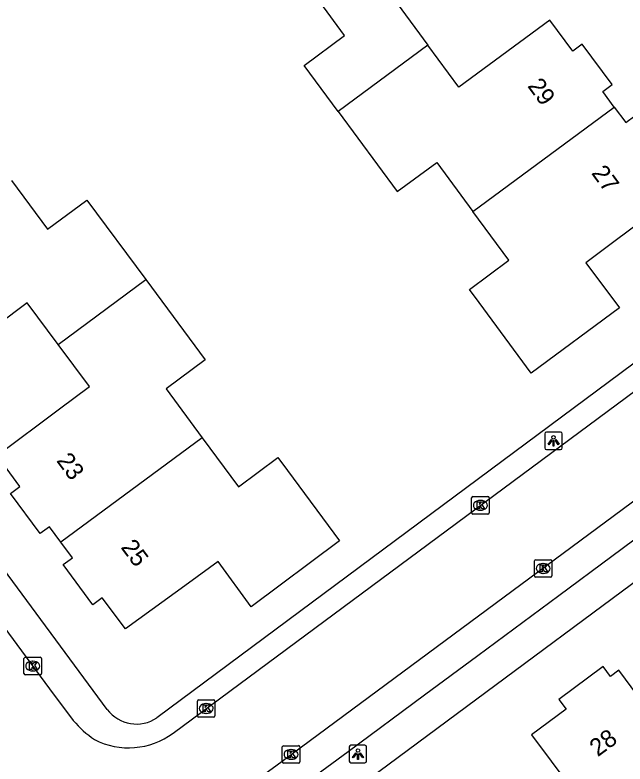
# Model space of a CAD drawing. Extents: x 163427 to 164190, y 380331 to 381641.
# Drawn here: x 163869.78 to 163904.63, y 381127.66 to 381170.43 of the extents above; entities that cross this region are included whole.
import ezdxf

# ---------------------------------------------------------------- set-up
doc = ezdxf.new("R2010")
doc.units = 0
for name, color, linetype in [('IMGEO_Kolk', 7, 'Continuous'), ('IMGEO_Lichtpunt', 7, 'Continuous'), ('IMGEO_Pand', 7, 'Continuous'), ('IMGEO_Pand_nummerreeks', 7, 'Continuous'), ('IMGEO_Rijbaan_lokaal_open', 7, 'Continuous'), ('IMGEO_Voetpad_open', 7, 'Continuous')]:
    doc.layers.add(name, color=color, linetype=linetype)

msp = doc.modelspace()

# ---------------------------------------------------------------- linework, layer by layer
at = {"layer": 'IMGEO_Kolk'}
for p, q in [((163895.865, 381142.004), (163895.865, 381142.856)), ((163895.94, 381142.93), (163896.792, 381142.93)), ((163896.866, 381142.856), (163896.866, 381142.004)), ((163896.353, 381142.71), (163896.378, 381142.71)), ((163896.792, 381141.93), (163895.94, 381141.93)), ((163896.376, 381142.15), (163896.351, 381142.15)), ((163899.526, 381139.324), (163900.378, 381139.324)), ((163899.451, 381138.398), (163899.451, 381139.25)), ((163899.939, 381139.104), (163899.964, 381139.104)), ((163900.452, 381139.25), (163900.452, 381138.398)), ((163899.962, 381138.544), (163899.937, 381138.544)), ((163900.378, 381138.324), (163899.526, 381138.324)), ((163870.372, 381133.748), (163871.224, 381133.748)), ((163870.297, 381132.822), (163870.297, 381133.674)), ((163870.785, 381133.528), (163870.81, 381133.528)), ((163871.298, 381133.674), (163871.298, 381132.822)), ((163870.808, 381132.968), (163870.783, 381132.968)), ((163871.224, 381132.748), (163870.372, 381132.748)), ((163880.205, 381130.401), (163880.205, 381131.253)), ((163880.28, 381131.327), (163881.132, 381131.327)), ((163881.206, 381131.253), (163881.206, 381130.401)), ((163880.693, 381131.107), (163880.718, 381131.107)), ((163881.132, 381130.327), (163880.28, 381130.327)), ((163880.716, 381130.547), (163880.691, 381130.547)), ((163885.052, 381127.777), (163885.052, 381128.629)), ((163885.127, 381128.703), (163885.979, 381128.703)), ((163886.053, 381128.629), (163886.053, 381127.777)), ((163885.54, 381128.483), (163885.565, 381128.483)), ((163885.563, 381127.923), (163885.538, 381127.923)), ((163885.979, 381127.703), (163885.127, 381127.703))]:
    msp.add_line(p, q, dxfattribs=at)
for points in [[(163895.865, 381142.004), (163895.865, 381142.856)], [(163895.94, 381142.93), (163896.792, 381142.93)], [(163896.866, 381142.856), (163896.866, 381142.004)], [(163896.186, 381142.63), (163896.309, 381142.63), (163896.309, 381142.479), (163896.439, 381142.63), (163896.603, 381142.63), (163896.457, 381142.479), (163896.61, 381142.23), (163896.458, 381142.23), (163896.373, 381142.394), (163896.309, 381142.327), (163896.309, 381142.23), (163896.186, 381142.23), (163896.186, 381142.63)], [(163896.792, 381141.93), (163895.94, 381141.93)], [(163899.526, 381139.324), (163900.378, 381139.324)], [(163899.451, 381138.398), (163899.451, 381139.25)], [(163899.772, 381139.024), (163899.895, 381139.024), (163899.895, 381138.873), (163900.025, 381139.024), (163900.189, 381139.024), (163900.043, 381138.873), (163900.196, 381138.624), (163900.044, 381138.624), (163899.959, 381138.788), (163899.895, 381138.721), (163899.895, 381138.624), (163899.772, 381138.624), (163899.772, 381139.024)], [(163900.452, 381139.25), (163900.452, 381138.398)], [(163900.378, 381138.324), (163899.526, 381138.324)], [(163870.372, 381133.748), (163871.224, 381133.748)], [(163870.297, 381132.822), (163870.297, 381133.674)], [(163870.618, 381133.448), (163870.741, 381133.448), (163870.741, 381133.297), (163870.871, 381133.448), (163871.035, 381133.448), (163870.889, 381133.297), (163871.042, 381133.048), (163870.89, 381133.048), (163870.805, 381133.212), (163870.741, 381133.145), (163870.741, 381133.048), (163870.618, 381133.048), (163870.618, 381133.448)], [(163871.298, 381133.674), (163871.298, 381132.822)], [(163871.224, 381132.748), (163870.372, 381132.748)], [(163880.205, 381130.401), (163880.205, 381131.253)], [(163880.28, 381131.327), (163881.132, 381131.327)], [(163881.206, 381131.253), (163881.206, 381130.401)], [(163880.526, 381131.027), (163880.649, 381131.027), (163880.649, 381130.876), (163880.779, 381131.027), (163880.943, 381131.027), (163880.797, 381130.876), (163880.95, 381130.627), (163880.798, 381130.627), (163880.713, 381130.791), (163880.649, 381130.724), (163880.649, 381130.627), (163880.526, 381130.627), (163880.526, 381131.027)], [(163881.132, 381130.327), (163880.28, 381130.327)], [(163885.052, 381127.777), (163885.052, 381128.629)], [(163885.127, 381128.703), (163885.979, 381128.703)], [(163886.053, 381128.629), (163886.053, 381127.777)], [(163885.373, 381128.403), (163885.496, 381128.403), (163885.496, 381128.252), (163885.626, 381128.403), (163885.79, 381128.403), (163885.644, 381128.252), (163885.797, 381128.003), (163885.645, 381128.003), (163885.56, 381128.167), (163885.496, 381128.1), (163885.496, 381128.003), (163885.373, 381128.003), (163885.373, 381128.403)], [(163885.979, 381127.703), (163885.127, 381127.703)]]:
    msp.add_lwpolyline(points, dxfattribs=at)
for centre, start, end in [((163895.942, 381142.854), 91.552, 178.448), ((163895.942, 381142.854), 91.552, 178.448), ((163896.79, 381142.854), 1.552, 88.448), ((163896.79, 381142.854), 1.552, 88.448), ((163895.942, 381142.006), 181.552, 268.448), ((163895.942, 381142.006), 181.552, 268.448), ((163896.79, 381142.006), 271.552, 358.448), ((163896.79, 381142.006), 271.552, 358.448), ((163899.528, 381139.248), 91.552, 178.448), ((163899.528, 381139.248), 91.552, 178.448), ((163900.376, 381139.248), 1.552, 88.448), ((163900.376, 381139.248), 1.552, 88.448), ((163899.528, 381138.4), 181.552, 268.448), ((163899.528, 381138.4), 181.552, 268.448), ((163900.376, 381138.4), 271.552, 358.448), ((163900.376, 381138.4), 271.552, 358.448), ((163870.374, 381133.672), 91.552, 178.448), ((163870.374, 381133.672), 91.552, 178.448), ((163871.222, 381133.672), 1.552, 88.448), ((163871.222, 381133.672), 1.552, 88.448), ((163870.374, 381132.824), 181.552, 268.448), ((163870.374, 381132.824), 181.552, 268.448), ((163871.222, 381132.824), 271.552, 358.448), ((163871.222, 381132.824), 271.552, 358.448), ((163880.282, 381131.251), 91.552, 178.448), ((163880.282, 381131.251), 91.552, 178.448), ((163881.13, 381131.251), 1.552, 88.448), ((163881.13, 381131.251), 1.552, 88.448), ((163880.282, 381130.403), 181.552, 268.448), ((163880.282, 381130.403), 181.552, 268.448), ((163881.13, 381130.403), 271.552, 358.448), ((163881.13, 381130.403), 271.552, 358.448), ((163885.129, 381128.627), 91.552, 178.448), ((163885.129, 381128.627), 91.552, 178.448), ((163885.977, 381128.627), 1.552, 88.448), ((163885.977, 381128.627), 1.552, 88.448), ((163885.129, 381127.779), 181.552, 268.448), ((163885.129, 381127.779), 181.552, 268.448), ((163885.977, 381127.779), 271.552, 358.448), ((163885.977, 381127.779), 271.552, 358.448)]:
    msp.add_arc(centre, 0.0765, start, end, dxfattribs=at)
for centre, major_axis, ratio, start_param, end_param in [((163896.352, 381142.43), (-0.387, 0.002), 0.722429, 4.712389, 7.853982), ((163896.377, 381142.43), (-0.39, 0.002), 0.717154, 1.570796, 4.712389), ((163899.938, 381138.824), (-0.387, 0.002), 0.722429, 4.712389, 7.853982), ((163899.963, 381138.824), (-0.39, 0.002), 0.717154, 1.570796, 4.712389), ((163870.784, 381133.248), (-0.387, 0.002), 0.722429, 4.712389, 7.853982), ((163870.809, 381133.248), (-0.39, 0.002), 0.717154, 1.570796, 4.712389), ((163880.692, 381130.827), (-0.387, 0.002), 0.722429, 4.712389, 7.853982), ((163880.717, 381130.827), (-0.39, 0.002), 0.717154, 1.570796, 4.712389), ((163885.539, 381128.203), (-0.387, 0.002), 0.722429, 4.712389, 7.853982), ((163885.564, 381128.203), (-0.39, 0.002), 0.717154, 1.570796, 4.712389)]:
    msp.add_ellipse(centre, major_axis=major_axis, ratio=ratio, start_param=start_param, end_param=end_param, dxfattribs=at)
at = {"layer": 'IMGEO_Lichtpunt'}
for p, q in [((163900.948, 381146.612), (163900.14, 381146.612)), ((163900.948, 381146.612), (163900.14, 381146.612)), ((163900.046, 381146.517), (163900.046, 381145.71)), ((163900.046, 381146.517), (163900.046, 381145.71)), ((163901.042, 381145.71), (163901.042, 381146.517)), ((163901.042, 381145.71), (163901.042, 381146.517)), ((163900.14, 381145.616), (163900.948, 381145.616)), ((163900.14, 381145.616), (163900.948, 381145.616)), ((163888.873, 381128.628), (163888.873, 381127.821)), ((163888.873, 381128.628), (163888.873, 381127.821)), ((163889.775, 381128.723), (163888.967, 381128.723)), ((163889.775, 381128.723), (163888.967, 381128.723)), ((163889.869, 381127.821), (163889.869, 381128.628)), ((163889.869, 381127.821), (163889.869, 381128.628)), ((163888.967, 381127.727), (163889.775, 381127.727)), ((163888.967, 381127.727), (163889.775, 381127.727))]:
    msp.add_line(p, q, dxfattribs=at)
for points in [[(163900.42, 381146.181), (163900.459, 381146.153), (163900.271, 381145.891), (163900.233, 381145.918), (163900.42, 381146.181)], [(163900.632, 381146.153), (163900.67, 381146.18), (163900.857, 381145.918), (163900.818, 381145.89), (163900.632, 381146.153)], [(163900.522, 381146.133), (163900.569, 381146.133), (163900.569, 381145.811), (163900.522, 381145.811), (163900.522, 381146.133)], [(163889.247, 381128.292), (163889.286, 381128.264), (163889.098, 381128.002), (163889.06, 381128.029), (163889.247, 381128.292)], [(163889.349, 381128.244), (163889.396, 381128.244), (163889.396, 381127.922), (163889.349, 381127.922), (163889.349, 381128.244)], [(163889.459, 381128.264), (163889.497, 381128.291), (163889.684, 381128.029), (163889.645, 381128.001), (163889.459, 381128.264)]]:
    msp.add_lwpolyline(points, dxfattribs=at)
for centre in [(163900.545, 381146.315), (163889.372, 381128.426)]:
    msp.add_circle(centre, 0.0994, dxfattribs=at)
for centre, start, end in [((163900.14, 381146.517), 90, 180), ((163900.14, 381146.517), 90, 180), ((163900.948, 381146.517), 0, 90), ((163900.948, 381146.517), 0, 90), ((163900.14, 381145.71), 180, 270), ((163900.14, 381145.71), 180, 270), ((163900.948, 381145.71), 270, 0), ((163900.948, 381145.71), 270, 360), ((163888.967, 381128.628), 90, 180), ((163888.967, 381128.628), 90, 180), ((163889.775, 381128.628), 0, 90), ((163889.775, 381128.628), 0, 90), ((163888.967, 381127.821), 180, 270), ((163888.967, 381127.821), 180, 270), ((163889.775, 381127.821), 270, 0), ((163889.775, 381127.821), 270, 360)]:
    msp.add_arc(centre, 0.0946, start, end, dxfattribs=at)
at = {"layer": 'IMGEO_Pand'}
for points in [[(163895.984, 381181.97), (163898.336, 381178.777), (163897.808, 381178.385), (163899.116, 381176.624), (163891.604, 381171.094), (163893.368, 381168.698)], [(163888.24, 381164.922), (163886.3, 381167.548), (163888.607, 381169.253), (163887.188, 381171.174), (163889.447, 381172.843), (163887.383, 381175.637)], [(163904.008, 381165.174), (163903.352, 381166.064), (163903.884, 381166.456), (163902.178, 381168.769), (163901.651, 381168.373), (163900.332, 381170.131), (163895.131, 381166.302), (163893.368, 381168.698)], [(163893.368, 381168.698), (163888.24, 381164.922)], [(163904.008, 381165.174), (163904.665, 381164.283), (163905.197, 381164.676), (163906.897, 381162.371), (163906.356, 381161.988), (163907.631, 381160.185), (163904.073, 381157.531), (163902.39, 381156.275), (163904.312, 381153.699), (163899.276, 381149.981), (163896.305, 381154.003), (163895.748, 381154.757), (163898, 381156.42), (163895.936, 381159.214)], [(163895.936, 381159.214), (163904.008, 381165.174)], [(163888.24, 381164.922), (163891.621, 381160.344), (163893.872, 381162.007), (163895.936, 381159.214)], [(163869.581, 381160.987), (163871.647, 381158.2), (163873.888, 381159.861), (163877.25, 381155.325)], [(163872.254, 381151.606), (163877.25, 381155.325)], [(163877.25, 381155.325), (163880.651, 381150.737), (163878.411, 381149.076), (163880.48, 381146.285)], [(163872.254, 381151.606), (163870.475, 381153.999), (163868.764, 381152.726), (163865.197, 381150.072), (163863.893, 381151.842), (163863.362, 381151.451), (163861.664, 381153.74), (163862.196, 381154.135), (163861.533, 381155.029)], [(163872.408, 381140.322), (163871.754, 381141.206), (163871.224, 381140.814), (163869.523, 381143.111), (163870.056, 381143.503), (163868.749, 381145.28), (163872.325, 381147.94), (163874.035, 381149.212), (163872.254, 381151.606)], [(163880.48, 381146.285), (163882.549, 381143.494), (163884.789, 381145.156), (163885.342, 381144.41), (163888.32, 381140.393), (163883.272, 381136.64), (163881.394, 381139.227), (163879.691, 381137.99), (163876.101, 381135.383), (163874.767, 381137.141), (163874.239, 381136.741), (163872.532, 381139.046), (163873.062, 381139.439), (163872.408, 381140.322)], [(163880.48, 381146.285), (163872.408, 381140.322)], [(163911.457, 381128.826), (163908.835, 381126.878), (163907.537, 381128.624), (163904.279, 381133.006), (163903.797, 381132.65), (163903.374, 381133.22), (163900.854, 381131.347), (163901.27, 381130.787), (163899.295, 381129.331), (163903.828, 381123.229)]]:
    msp.add_lwpolyline(points, dxfattribs=at)
at = {"layer": 'IMGEO_Rijbaan_lokaal_open'}
for points in [[(163878.809, 381129.42), (163911.186, 381153.408)], [(163880.923, 381124.832), (163884.68, 381127.548), (163916.554, 381151.141)], [(163859.374, 381148.746), (163860.525, 381147.119), (163864.123, 381142.29), (163871.759, 381131.945), (163873.116, 381130.132)]]:
    msp.add_lwpolyline(points, dxfattribs=at)
for centre, radius, start, end in [((163878.04, 381134.419), 6.529, 221.042, 235.2732), ((163876.27, 381132.847), 4.266, 242.8159, 306.5339)]:
    msp.add_arc(centre, radius, start, end, dxfattribs=at)
at = {"layer": 'IMGEO_Voetpad_open'}
for points in [[(163875.058, 381130.776), (163855.129, 381157.768), (163853.96, 381156.776), (163839.528, 381176.358)], [(163911.894, 381155.545), (163877.893, 381130.301)], [(163915.45, 381148.075), (163911.422, 381145.095), (163908.391, 381142.852), (163903.871, 381139.507), (163900.842, 381137.267), (163896.214, 381133.842), (163893.166, 381131.587), (163888.806, 381128.36), (163885.739, 381126.089), (163884.183, 381124.937)], [(163882.189, 381120.998), (163883.08, 381121.66), (163884.455, 381122.693), (163917.22, 381146.987)]]:
    msp.add_lwpolyline(points, dxfattribs=at)
msp.add_arc((163876.722, 381132.011), 2.072, 216.5753, 304.4017, dxfattribs=at)

# ---------------------------------------------------------------- texts
at = {"layer": 'IMGEO_Pand_nummerreeks'}
for s, rotation, p in [('29', 306.2736, (163899.024, 381166.37)), ('27', 306.2737, (163902.673, 381161.397)), ('23', 306.6061, (163872.118, 381144.972)), ('25', 306.6061, (163875.794, 381140.024)), ('28', 36.4057, (163903.072, 381128.04))]:
    msp.add_text(s, height=1, rotation=rotation, dxfattribs=at).set_placement(p)

doc.saveas('drawing.dxf')
